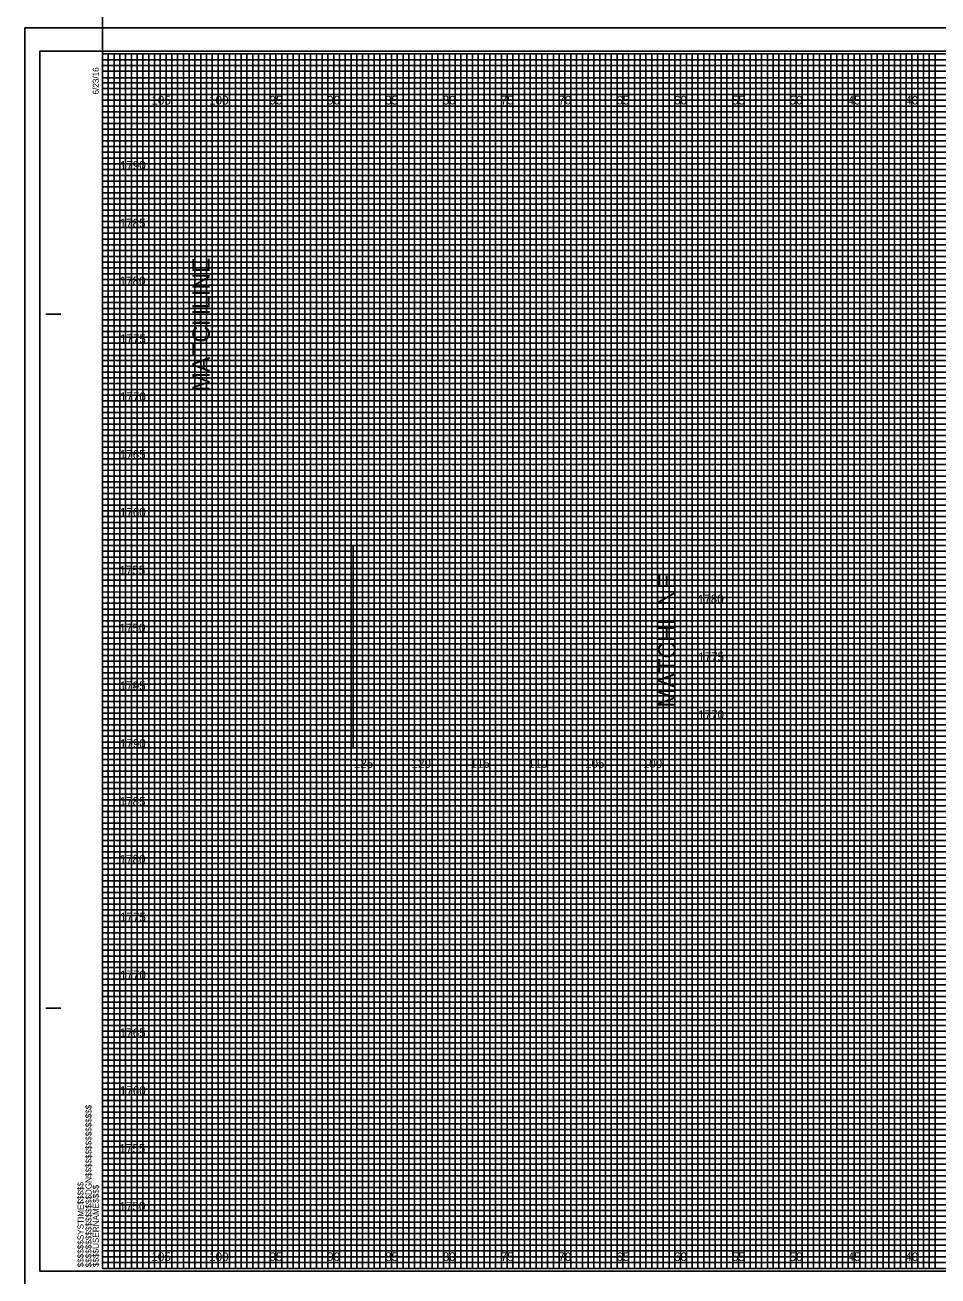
# Model space of a CAD drawing. Extents: x -7 to 392, y -2 to 440.
# Drawn here: x 223.6 to 302.5, y 222.5 to 330.7 of the extents above; entities that cross this region are included whole.
import ezdxf

# ---------------------------------------------------------------- set-up
doc = ezdxf.new("R2010")
doc.units = 0
for name, color, linetype in [('Matchline', 7, 'Continuous'), ('Matchline Text', 7, 'Continuous'), ('Prop Grid Mask', 7, 'Continuous'), ('Prop PFL Text', 7, 'Continuous'), ('Prop XS Elevation Labels', 7, 'Continuous'), ('Scratch_Level_3', 7, 'Continuous'), ('Scratch_Level_5', 7, 'Continuous'), ('Sheet Cross Section CELL', 7, 'Continuous'), ('Sheet Cross Section Grid Major CELL', 7, 'Continuous'), ('Sheet Cross Section Grid Middle CELL', 7, 'Continuous'), ('Sheet Cross Section Grid Minor 1 CELL', 7, 'Continuous'), ('Sheet Cross Section Grid Minor 2 CELL', 7, 'Continuous'), ('Sheet Cutting Line CELL', 7, 'Continuous'), ('Sheet DOT Grid CELL', 7, 'Continuous'), ('Sheet Plot Border Inside CELL', 7, 'Continuous'), ('Sheet Plot Border Outside CELL', 7, 'Continuous')]:
    doc.layers.add(name, color=color, linetype=linetype)

msp = doc.modelspace()

# ---------------------------------------------------------------- linework, layer by layer
at = {"layer": 'Matchline'}
for p, q in [((240.26, 295.71), (240.26, 313.21)), ((277.76, 268.21), (277.76, 285.71))]:
    msp.add_line(p, q, dxfattribs=at)
at = {"layer": 'Prop PFL Text'}
msp.add_line((230.26, 333.21), (230.26, 328.21), dxfattribs=at)
at = {"layer": 'Scratch_Level_3'}
for p, q in [((252.76, 268.21), (252.76, 285.71)), ((257.76, 268.21), (257.76, 285.71)), ((262.76, 268.21), (262.76, 285.71)), ((267.76, 268.21), (267.76, 285.71)), ((272.76, 268.21), (272.76, 285.71))]:
    msp.add_line(p, q, dxfattribs=at)
at = {"layer": 'Scratch_Level_5'}
for points in [[(240.26, 313.21), (230.26, 313.21), (230.26, 295.71), (240.26, 295.71)], [(277.76, 285.71), (251.93, 285.71), (251.93, 268.21), (277.76, 268.21)]]:
    msp.add_lwpolyline(points, close=True, dxfattribs=at)
at = {"layer": 'Sheet Cross Section CELL'}
for p, q in [((225.36, 305.71), (226.61, 305.71)), ((225.41, 305.71), (226.66, 305.71)), ((225.36, 245.71), (226.61, 245.71)), ((225.41, 245.71), (226.66, 245.71)), ((230.26, 223.21), (230.26, 223.21)), ((230.26, 223.21), (230.26, 223.21)), ((230.26, 223.21), (230.26, 223.21)), ((230.26, 223.21), (230.26, 223.21)), ((230.26, 223.21), (230.26, 223.21)), ((230.26, 223.21), (230.26, 223.21)), ((230.26, 223.21), (230.26, 223.21))]:
    msp.add_line(p, q, dxfattribs=at)
msp.add_lwpolyline([(390.26, 328.21), (230.26, 328.21), (230.26, 223.21), (390.26, 223.21)], close=True, dxfattribs=at)
at = {"layer": 'Sheet Cross Section Grid Major CELL'}
for p, q in [((235.26, 328.21), (230.26, 328.21)), ((235.26, 223.21), (235.26, 328.21)), ((245.26, 328.21), (240.26, 328.21)), ((240.26, 328.21), (240.26, 223.21)), ((245.26, 223.21), (245.26, 328.21)), ((255.26, 328.21), (250.26, 328.21)), ((250.26, 328.21), (250.26, 223.21)), ((255.26, 223.21), (255.26, 328.21)), ((265.26, 328.21), (260.26, 328.21)), ((260.26, 328.21), (260.26, 223.21)), ((265.26, 223.21), (265.26, 328.21)), ((275.26, 328.21), (270.26, 328.21)), ((270.26, 328.21), (270.26, 223.21)), ((275.26, 223.21), (275.26, 328.21)), ((285.26, 328.21), (280.26, 328.21)), ((280.26, 328.21), (280.26, 223.21)), ((285.26, 223.21), (285.26, 328.21)), ((295.26, 328.21), (290.26, 328.21)), ((290.26, 328.21), (290.26, 223.21)), ((295.26, 223.21), (295.26, 328.21)), ((305.26, 328.21), (300.26, 328.21)), ((300.26, 328.21), (300.26, 223.21)), ((240.26, 223.21), (235.26, 223.21)), ((250.26, 223.21), (245.26, 223.21)), ((260.26, 223.21), (255.26, 223.21)), ((270.26, 223.21), (265.26, 223.21)), ((280.26, 223.21), (275.26, 223.21)), ((290.26, 223.21), (285.26, 223.21)), ((300.26, 223.21), (295.26, 223.21))]:
    msp.add_line(p, q, dxfattribs=at)
for points in [[(230.26, 323.21), (390.26, 323.21), (390.26, 318.21), (230.26, 318.21)], [(230.26, 313.21), (390.26, 313.21), (390.26, 308.21), (230.26, 308.21)], [(230.26, 303.21), (390.26, 303.21), (390.26, 298.21), (230.26, 298.21)], [(230.26, 293.21), (390.26, 293.21), (390.26, 288.21), (230.26, 288.21)], [(230.26, 283.21), (390.26, 283.21), (390.26, 278.21), (230.26, 278.21)], [(230.26, 273.21), (390.26, 273.21), (390.26, 268.21), (230.26, 268.21)], [(230.26, 263.21), (390.26, 263.21), (390.26, 258.21), (230.26, 258.21)], [(230.26, 253.21), (390.26, 253.21), (390.26, 248.21), (230.26, 248.21)], [(230.26, 243.21), (390.26, 243.21), (390.26, 238.21), (230.26, 238.21)], [(230.26, 233.21), (390.26, 233.21), (390.26, 228.21), (230.26, 228.21)]]:
    msp.add_lwpolyline(points, dxfattribs=at)
at = {"layer": 'Sheet Cross Section Grid Middle CELL'}
for points in [[(230.26, 328.21), (232.76, 328.21), (232.76, 223.21), (237.76, 223.21), (237.76, 328.21), (242.76, 328.21), (242.76, 223.21), (247.76, 223.21), (247.76, 328.21), (252.76, 328.21), (252.76, 223.21), (257.76, 223.21), (257.76, 328.21), (262.76, 328.21), (262.76, 223.21), (267.76, 223.21), (267.76, 328.21), (272.76, 328.21), (272.76, 223.21), (277.76, 223.21), (277.76, 328.21), (282.76, 328.21), (282.76, 223.21), (287.76, 223.21), (287.76, 328.21), (292.76, 328.21), (292.76, 223.21), (297.76, 223.21), (297.76, 328.21), (302.76, 328.21)], [(230.26, 325.71), (367.76, 325.71)], [(230.26, 315.71), (390.26, 315.71), (390.26, 320.71), (230.26, 320.71)], [(230.26, 305.71), (390.26, 305.71), (390.26, 310.71), (230.26, 310.71)], [(230.26, 295.71), (390.26, 295.71), (390.26, 300.71), (230.26, 300.71)], [(230.26, 285.71), (390.26, 285.71), (390.26, 290.71), (230.26, 290.71)], [(230.26, 275.71), (390.26, 275.71), (390.26, 280.71), (230.26, 280.71)], [(230.26, 265.71), (390.26, 265.71), (390.26, 270.71), (230.26, 270.71)], [(230.26, 255.71), (390.26, 255.71), (390.26, 260.71), (230.26, 260.71)], [(230.26, 245.71), (390.26, 245.71), (390.26, 250.71), (230.26, 250.71)], [(230.26, 235.71), (390.26, 235.71), (390.26, 240.71), (230.26, 240.71)], [(230.26, 225.71), (390.26, 225.71), (390.26, 230.71), (230.26, 230.71)]]:
    msp.add_lwpolyline(points, dxfattribs=at)
at = {"layer": 'Sheet Cross Section Grid Minor 1 CELL'}
for p, q in [((230.26, 327.71), (360.26, 327.71)), ((360.26, 327.2), (230.26, 327.2)), ((230.26, 327.2), (230.26, 326.71)), ((230.26, 326.71), (360.26, 326.71)), ((360.26, 326.16), (230.26, 326.16)), ((230.26, 326.16), (230.26, 325.21)), ((230.26, 325.21), (390.26, 325.21))]:
    msp.add_line(p, q, dxfattribs=at)
for points in [[(230.26, 324.71), (365.26, 324.71), (390.26, 324.71), (390.26, 324.21), (230.26, 324.21)], [(230.26, 323.71), (390.26, 323.71), (390.26, 322.71), (230.26, 322.71)], [(230.26, 322.21), (390.26, 322.21), (390.26, 321.71), (230.26, 321.7)], [(230.26, 321.21), (390.26, 321.21), (390.26, 320.21), (230.26, 320.21)], [(230.26, 319.71), (390.26, 319.71), (390.26, 319.21), (230.26, 319.21)], [(230.26, 318.71), (390.26, 318.71), (390.26, 317.71), (230.26, 317.71)], [(230.26, 317.21), (390.26, 317.21), (390.26, 316.71), (230.26, 316.71)], [(230.26, 316.21), (390.26, 316.21), (390.26, 315.21), (230.26, 315.21)], [(230.26, 314.71), (390.26, 314.71), (390.26, 314.21), (230.26, 314.21)], [(230.26, 313.71), (390.26, 313.71), (390.26, 312.71), (230.26, 312.71)], [(230.26, 312.21), (390.26, 312.21), (390.26, 311.71), (230.26, 311.71)], [(230.26, 311.21), (390.26, 311.21), (390.26, 310.19), (390.26, 309.71), (390.26, 309.21), (230.26, 309.21)], [(230.26, 310.21), (390.26, 310.21), (390.26, 309.71), (230.26, 309.71)], [(230.26, 308.71), (390.26, 308.71), (390.26, 307.71), (230.26, 307.73)], [(230.26, 307.73), (390.26, 307.71), (390.26, 307.21), (230.26, 307.21)], [(230.26, 306.71), (390.26, 306.71), (390.26, 306.21), (230.26, 306.21)], [(230.26, 305.21), (390.26, 305.21), (390.26, 304.71), (230.26, 304.71)], [(230.26, 304.21), (390.26, 304.21), (390.26, 303.71), (230.26, 303.71)], [(230.23, 302.66), (390.26, 302.66), (390.26, 302.15), (230.23, 302.15)], [(230.26, 301.71), (390.26, 301.71), (390.26, 301.21), (230.26, 301.21)], [(230.26, 300.21), (390.26, 300.21), (390.26, 299.71), (230.26, 299.71)], [(230.26, 299.21), (390.26, 299.21), (390.26, 298.71), (230.26, 298.71)], [(230.26, 297.71), (390.26, 297.71), (390.26, 297.21), (230.26, 297.21)], [(230.26, 296.71), (390.26, 296.71), (390.26, 296.21), (230.26, 296.21)], [(230.26, 295.21), (390.26, 295.21), (390.26, 294.71), (230.26, 294.71)], [(230.26, 294.21), (390.26, 294.21), (390.26, 293.71), (230.26, 293.71)], [(230.26, 292.71), (390.26, 292.71), (390.26, 292.2), (230.26, 292.21)], [(230.26, 291.71), (390.26, 291.71), (390.26, 291.21), (230.26, 291.21)], [(230.26, 290.21), (390.26, 290.21), (390.26, 289.71), (230.26, 289.71)], [(230.26, 289.21), (390.26, 289.21), (390.26, 288.71), (230.26, 288.71)], [(230.26, 287.71), (390.26, 287.71), (390.26, 287.21), (230.26, 287.21)], [(230.26, 286.71), (390.26, 286.71), (390.26, 286.21), (230.26, 286.21)], [(230.26, 285.21), (390.26, 285.21), (390.26, 284.71), (230.26, 284.71)], [(230.26, 284.21), (390.26, 284.21), (390.26, 283.71), (230.26, 283.71)], [(230.26, 282.71), (390.26, 282.71), (390.26, 282.21), (230.26, 282.21)], [(230.26, 281.71), (390.3, 281.67), (390.26, 281.21), (230.26, 281.21)], [(230.26, 280.21), (390.26, 280.21), (390.26, 279.71), (230.26, 279.71)], [(230.26, 279.21), (390.26, 279.21), (390.26, 278.71), (230.26, 278.71)], [(230.26, 277.71), (390.26, 277.71), (390.26, 277.21), (230.26, 277.21)], [(230.26, 276.71), (390.26, 276.71), (390.26, 276.21), (230.26, 276.21)], [(230.26, 275.21), (390.26, 275.21), (390.26, 274.71), (230.26, 274.71)], [(230.26, 274.21), (390.26, 274.21), (390.26, 273.71), (230.26, 273.71)], [(230.26, 272.71), (390.26, 272.71), (390.26, 272.21), (230.26, 272.21)], [(230.26, 271.71), (390.26, 271.71), (390.26, 271.21), (230.26, 271.21)], [(230.26, 270.21), (390.26, 270.21), (390.26, 269.71), (230.26, 269.71)], [(230.26, 269.21), (390.26, 269.21), (390.26, 268.71), (230.26, 268.71)], [(230.26, 267.71), (390.26, 267.71), (390.26, 267.21), (230.26, 267.21)], [(230.26, 266.71), (390.26, 266.71), (390.26, 266.21), (230.26, 266.21)], [(230.26, 265.21), (390.26, 265.21), (390.26, 264.71), (230.26, 264.71)], [(230.26, 264.21), (390.26, 264.21), (390.26, 263.71), (230.26, 263.71)], [(230.26, 262.71), (390.26, 262.71), (390.26, 262.2), (230.26, 262.21)], [(230.26, 261.71), (390.26, 261.71), (390.26, 261.21), (230.26, 261.21)], [(230.26, 260.21), (390.26, 260.21), (390.26, 259.71), (230.26, 259.71)], [(230.26, 259.21), (390.26, 259.21), (390.26, 258.71), (230.26, 258.71)], [(230.26, 257.71), (390.26, 257.71), (390.26, 257.21), (230.26, 257.21)], [(230.26, 256.71), (390.26, 256.71), (390.26, 256.21), (230.26, 256.21)], [(230.26, 255.21), (390.26, 255.21), (390.26, 254.71), (230.26, 254.71)], [(230.26, 254.21), (390.26, 254.21), (390.26, 253.71), (230.26, 253.71)], [(230.26, 252.71), (390.26, 252.71), (390.26, 252.21), (230.26, 252.21)], [(230.26, 251.71), (390.3, 251.67), (390.26, 251.21), (230.26, 251.21)], [(230.26, 250.21), (390.26, 250.21), (390.26, 249.71), (230.26, 249.71)], [(230.26, 249.21), (390.26, 249.21), (390.26, 248.71), (230.26, 248.71)], [(230.26, 247.71), (390.26, 247.71), (390.26, 247.21), (230.26, 247.21)], [(230.26, 246.71), (390.26, 246.71), (390.26, 246.21), (230.26, 246.21)], [(230.26, 245.21), (390.26, 245.21), (390.26, 244.71), (230.26, 244.71)], [(230.26, 244.21), (390.26, 244.21), (390.26, 243.71), (230.26, 243.71)], [(230.26, 242.71), (390.26, 242.71), (390.26, 242.21), (230.26, 242.21)], [(230.26, 241.71), (390.26, 241.71), (390.26, 241.21), (230.26, 241.21)], [(230.26, 240.21), (390.26, 240.21), (390.26, 239.71), (230.26, 239.71)], [(230.26, 239.21), (390.26, 239.21), (390.26, 238.71), (230.26, 238.71)], [(230.26, 237.71), (390.26, 237.71), (390.26, 237.21), (230.26, 237.21)], [(230.26, 236.71), (390.26, 236.71), (390.26, 236.21), (230.26, 236.21)], [(230.26, 235.21), (390.26, 235.21), (390.26, 234.71), (230.26, 234.71)], [(230.26, 234.21), (390.26, 234.21), (390.26, 233.71), (230.26, 233.71)], [(230.26, 232.71), (390.26, 232.71), (390.26, 232.21), (230.26, 232.21)], [(230.26, 231.71), (390.26, 231.71), (390.26, 231.21), (230.26, 231.21)], [(230.26, 230.21), (390.26, 230.21), (390.26, 229.71), (230.26, 229.71)], [(230.26, 229.21), (390.26, 229.21), (390.26, 228.71), (230.26, 228.71)], [(230.26, 227.71), (390.26, 227.71), (390.26, 227.21), (230.26, 227.21)], [(230.26, 226.71), (390.26, 226.71), (390.26, 226.21), (230.26, 226.21)], [(230.26, 225.21), (390.26, 225.21), (390.26, 224.71), (230.26, 224.71)], [(230.26, 224.21), (390.26, 224.21), (390.26, 223.71), (230.26, 223.71)]]:
    msp.add_lwpolyline(points, dxfattribs=at)
at = {"layer": 'Sheet Cross Section Grid Minor 2 CELL'}
for points in [[(230.26, 223.21), (230.76, 223.21), (230.76, 328.21), (231.26, 328.21), (231.26, 223.21)], [(231.26, 223.21), (231.76, 223.21), (231.76, 328.21), (232.26, 328.21), (232.26, 223.21)], [(232.76, 223.21), (233.26, 223.21), (233.26, 328.21), (233.76, 328.21), (233.76, 223.21)], [(233.76, 223.21), (234.26, 223.21), (234.26, 328.21), (234.76, 328.21), (234.76, 223.21)], [(235.26, 223.21), (235.76, 223.21), (235.76, 328.21), (236.26, 328.21), (236.26, 223.21)], [(236.26, 223.21), (236.76, 223.21), (236.76, 328.21), (237.26, 328.21), (237.26, 223.21)], [(237.76, 223.21), (238.26, 223.21), (238.26, 328.21), (238.76, 328.21), (238.76, 223.21)], [(238.76, 223.21), (239.26, 223.21), (239.26, 328.21), (239.76, 328.21), (239.76, 223.21)], [(240.26, 223.21), (240.76, 223.21), (240.76, 328.21), (241.26, 328.21), (241.26, 223.21)], [(241.26, 223.21), (241.76, 223.21), (241.76, 328.21), (242.26, 328.21), (242.26, 223.21)], [(242.76, 223.21), (243.26, 223.21), (243.26, 328.21), (243.76, 328.21), (243.76, 223.21)], [(243.76, 223.21), (244.26, 223.21), (244.26, 328.21), (244.76, 328.21), (244.76, 223.21)], [(245.26, 223.21), (245.76, 223.21), (245.76, 328.21), (246.26, 328.21), (246.26, 223.21)], [(246.26, 223.21), (246.76, 223.21), (246.76, 328.21), (247.26, 328.21), (247.26, 223.21)], [(247.76, 223.21), (248.26, 223.21), (248.26, 328.21), (248.76, 328.21), (248.76, 223.21)], [(248.76, 223.21), (249.26, 223.21), (249.26, 328.21), (249.76, 328.21), (249.76, 223.21)], [(250.26, 223.21), (250.76, 223.21), (250.76, 328.21), (251.26, 328.21), (251.26, 223.21)], [(251.26, 223.21), (251.76, 223.21), (251.76, 328.21), (252.26, 328.21), (252.26, 223.21)], [(252.76, 223.21), (253.26, 223.21), (253.26, 328.21), (253.76, 328.21), (253.76, 223.21)], [(253.76, 223.21), (254.26, 223.21), (254.26, 328.21), (254.76, 328.21), (254.76, 223.21)], [(255.26, 223.21), (255.76, 223.21), (255.76, 328.21), (256.26, 328.21), (256.26, 223.21)], [(256.26, 223.21), (256.76, 223.21), (256.76, 328.21), (257.26, 328.21), (257.26, 223.21)], [(257.76, 223.21), (258.26, 223.21), (258.26, 328.21), (258.76, 328.21), (258.76, 223.21)], [(258.76, 223.21), (259.26, 223.21), (259.26, 328.21), (259.76, 328.21), (259.76, 223.21)], [(260.26, 223.21), (260.76, 223.21), (260.76, 328.21), (261.26, 328.21), (261.26, 223.21)], [(261.26, 223.21), (261.76, 223.21), (261.76, 328.21), (262.26, 328.21), (262.26, 223.21)], [(262.76, 223.21), (263.26, 223.21), (263.26, 328.21), (263.76, 328.21), (263.76, 223.21)], [(263.76, 223.21), (264.26, 223.21), (264.26, 328.21), (264.76, 328.21), (264.76, 223.21)], [(265.26, 223.21), (265.76, 223.21), (265.76, 328.21), (266.26, 328.21), (266.26, 223.21)], [(266.26, 223.21), (266.76, 223.21), (266.76, 328.21), (267.26, 328.21), (267.26, 223.21)], [(267.76, 223.21), (268.26, 223.21), (268.26, 328.21), (268.76, 328.21), (268.76, 223.21)], [(268.76, 223.21), (269.26, 223.21), (269.26, 328.21), (269.76, 328.21), (269.76, 223.21)], [(270.26, 223.21), (270.76, 223.21), (270.76, 328.21), (271.26, 328.21), (271.26, 223.21)], [(271.26, 223.21), (271.76, 223.21), (271.76, 328.21), (272.26, 328.21), (272.26, 223.21)], [(272.76, 223.21), (273.26, 223.21), (273.26, 328.21), (273.76, 328.21), (273.76, 223.21)], [(273.76, 223.21), (274.26, 223.21), (274.26, 328.21), (274.76, 328.21), (274.76, 223.21)], [(275.26, 223.21), (275.76, 223.21), (275.76, 328.21), (276.26, 328.21), (276.26, 223.21)], [(276.26, 223.21), (276.76, 223.21), (276.76, 328.21), (277.26, 328.21), (277.26, 223.21)], [(277.76, 223.21), (278.26, 223.21), (278.26, 328.21), (278.76, 328.21), (278.76, 223.21)], [(278.76, 223.21), (279.26, 223.21), (279.26, 328.21), (279.76, 328.21), (279.76, 223.21)], [(280.26, 223.21), (280.76, 223.21), (280.76, 328.21), (281.26, 328.21), (281.26, 223.21)], [(281.26, 223.21), (281.76, 223.21), (281.76, 328.21), (282.26, 328.21), (282.26, 223.21)], [(282.76, 223.21), (283.26, 223.21), (283.26, 328.21), (283.76, 328.21), (283.76, 223.21)], [(283.76, 223.21), (284.26, 223.21), (284.26, 328.21), (284.76, 328.21), (284.76, 223.21)], [(285.26, 223.21), (285.76, 223.21), (285.76, 328.21), (286.26, 328.21), (286.26, 223.21)], [(286.26, 223.21), (286.76, 223.21), (286.76, 328.21), (287.26, 328.21), (287.26, 223.21)], [(287.76, 223.21), (288.26, 223.21), (288.26, 328.21), (288.76, 328.21), (288.76, 223.21)], [(288.76, 223.21), (289.26, 223.21), (289.26, 328.21), (289.76, 328.21), (289.76, 223.21)], [(290.26, 223.21), (290.76, 223.21), (290.76, 328.21), (291.26, 328.21), (291.26, 223.21)], [(291.26, 223.21), (291.76, 223.21), (291.76, 328.21), (292.26, 328.21), (292.26, 223.21)], [(292.76, 223.21), (293.26, 223.21), (293.26, 328.21), (293.76, 328.21), (293.76, 223.21)], [(293.76, 223.21), (294.26, 223.21), (294.26, 328.21), (294.76, 328.21), (294.76, 223.21)], [(295.26, 223.21), (295.76, 223.21), (295.76, 328.21), (296.26, 328.21), (296.26, 223.21)], [(296.26, 223.21), (296.76, 223.21), (296.76, 328.21), (297.26, 328.21), (297.26, 223.21)], [(297.76, 223.21), (298.26, 223.21), (298.26, 328.21), (298.76, 328.21), (298.76, 223.21)], [(298.76, 223.21), (299.26, 223.21), (299.26, 328.21), (299.76, 328.21), (299.76, 223.21)], [(300.26, 223.21), (300.76, 223.21), (300.76, 328.21), (301.26, 328.21), (301.26, 223.21)], [(301.26, 223.21), (301.76, 223.21), (301.76, 328.21), (302.26, 328.21), (302.26, 223.21)]]:
    msp.add_lwpolyline(points, dxfattribs=at)
at = {"layer": 'Sheet Cutting Line CELL'}
for p, q in [((391.91, 330.46), (223.56, 330.46)), ((223.56, 330.46), (223.56, 220.96))]:
    msp.add_line(p, q, dxfattribs=at)
at = {"layer": 'Sheet DOT Grid CELL'}
for p, q in [((235.26, 223.21), (235.26, 328.21)), ((240.26, 223.21), (240.26, 328.21)), ((245.26, 223.21), (245.26, 328.21)), ((250.26, 223.21), (250.26, 328.21)), ((255.26, 223.21), (255.26, 328.21)), ((260.26, 223.21), (260.26, 328.21)), ((265.26, 223.21), (265.26, 328.21)), ((270.26, 223.21), (270.26, 328.21)), ((275.26, 223.21), (275.26, 328.21)), ((280.26, 223.21), (280.26, 328.21)), ((285.26, 223.21), (285.26, 328.21)), ((290.26, 223.21), (290.26, 328.21)), ((295.26, 223.21), (295.26, 328.21)), ((300.26, 223.21), (300.26, 328.21)), ((230.26, 323.21), (390.26, 323.21)), ((230.26, 318.21), (390.26, 318.21)), ((230.26, 313.21), (390.26, 313.21)), ((230.26, 308.21), (390.26, 308.21)), ((230.26, 303.21), (390.26, 303.21)), ((230.26, 298.21), (390.26, 298.21)), ((230.26, 293.21), (390.26, 293.21)), ((230.26, 288.21), (390.26, 288.21)), ((230.26, 283.21), (390.26, 283.21)), ((230.26, 278.21), (390.26, 278.21)), ((230.26, 273.21), (390.26, 273.21)), ((230.26, 268.21), (390.26, 268.21)), ((230.26, 263.21), (390.26, 263.21)), ((230.26, 258.21), (390.26, 258.21)), ((230.26, 253.21), (390.26, 253.21)), ((230.26, 248.21), (390.26, 248.21)), ((230.26, 243.21), (390.26, 243.21)), ((230.26, 238.21), (390.26, 238.21)), ((230.26, 233.21), (390.26, 233.21)), ((230.26, 228.21), (390.26, 228.21))]:
    msp.add_line(p, q, dxfattribs=at)
at = {"layer": 'Sheet Plot Border Inside CELL'}
msp.add_lwpolyline([(224.86, 222.96), (391.46, 222.96), (391.46, 328.46), (224.86, 328.46)], close=True, dxfattribs=at)
at = {"layer": 'Sheet Plot Border Outside CELL'}
msp.add_lwpolyline([(223.56, 220.96), (391.91, 220.96), (391.91, 330.46), (223.56, 330.46)], close=True, dxfattribs=at)

# ---------------------------------------------------------------- texts
at = {"layer": 'Matchline Text'}
for p in [(239.54, 299.02), (279.83, 271.7)]:
    msp.add_text('MATCHLINE', height=1.5, rotation=90, dxfattribs=at).set_placement(p)
at = {"layer": 'Prop Grid Mask'}
for s, p in [('105', (234.5, 323.84)), ('100', (239.49, 323.84)), ('95', (244.71, 323.84)), ('90', (249.69, 323.84)), ('85', (254.71, 323.84)), ('80', (259.69, 323.84)), ('75', (264.71, 323.84)), ('70', (269.69, 323.84)), ('65', (274.71, 323.84)), ('60', (279.69, 323.84)), ('55', (284.71, 323.84)), ('50', (289.69, 323.84)), ('45', (294.71, 323.84)), ('40', (299.69, 323.84)), ('125', (252, 266.49)), ('120', (256.99, 266.49)), ('115', (262.09, 266.49)), ('110', (267.08, 266.49)), ('105', (272, 266.49)), ('100', (276.99, 266.49)), ('105', (234.5, 223.84)), ('100', (239.49, 223.84)), ('95', (244.71, 223.84)), ('90', (249.69, 223.84)), ('85', (254.71, 223.84)), ('80', (259.69, 223.84)), ('75', (264.71, 223.84)), ('70', (269.69, 223.84)), ('65', (274.71, 223.84)), ('60', (279.69, 223.84)), ('55', (284.71, 223.84)), ('50', (289.69, 223.84)), ('45', (294.71, 223.84)), ('40', (299.69, 223.84))]:
    msp.add_text(s, height=0.75, dxfattribs=at).set_placement(p)
at = {"layer": 'Prop XS Elevation Labels'}
for s, p in [('1790', (231.77, 318.21)), ('1785', (231.75, 313.21)), ('1780', (231.75, 308.21)), ('1775', (231.78, 303.21)), ('1770', (231.78, 298.21)), ('1765', (231.76, 293.21)), ('1760', (231.77, 288.21)), ('1755', (231.73, 283.21)), ('1780', (281.75, 280.71)), ('1750', (231.74, 278.21)), ('1775', (281.78, 275.71)), ('1795', (231.76, 273.21)), ('1745', (231.76, 273.21)), ('1770', (281.78, 270.71)), ('1790', (231.77, 268.21)), ('1785', (231.75, 263.21)), ('1780', (231.75, 258.21)), ('1775', (231.78, 253.21)), ('1770', (231.78, 248.21)), ('1765', (231.76, 243.21)), ('1760', (231.77, 238.21)), ('1755', (231.73, 233.21)), ('1750', (231.74, 228.21))]:
    msp.add_text(s, height=0.75, dxfattribs=at).set_placement(p)
at = {"layer": 'Sheet Cross Section CELL'}
for s, p in [('6/23/16', (229.94, 324.71)), ('$$$$$$$$$$$$$$$$DGN$$$$$$$$$$$$$$$$', (229.32, 223.3)), ('$$$$$$SYSTIME$$$$$', (228.63, 223.3)), ('$$$$USERNAME$$$$', (229.95, 223.33))]:
    msp.add_text(s, height=0.525, rotation=90, dxfattribs=at).set_placement(p)

doc.saveas('drawing.dxf')
